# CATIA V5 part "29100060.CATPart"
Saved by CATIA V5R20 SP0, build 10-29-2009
Part number: 29100060
Definition: NONE
Nomenclature: 29100060
Source: Unknown
Description: 29100060
Bounding box of the stored display mesh (mm): x -30 to 44.548, y -64 to 98.548, z -54 to 54
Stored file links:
  C:\Users\Utente\Desktop\IO LAVORO\3D X SITO CF\X SITO\PLASTICA\RF1\29100060.CATPart
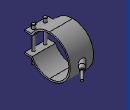
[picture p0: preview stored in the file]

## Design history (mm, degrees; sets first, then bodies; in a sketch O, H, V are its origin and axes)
Body1 "29100060" (main body)
  Solid1: solid without history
